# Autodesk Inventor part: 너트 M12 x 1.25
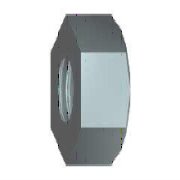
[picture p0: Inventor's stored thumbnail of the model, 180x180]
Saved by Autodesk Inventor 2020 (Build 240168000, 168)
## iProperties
Created: 2015-12
Part Number: 너트 M12 x 1.25
Material: 스테인리스강
Description: 6각 너트
Document SubType Name: Modeling
Standard: KS B 1012
Designer: mdu
Standards Organization: KS
Language: ko-KR
Size Designation: M12x1.25
Categories: <MemberInstance><Categories><Category DisplayName="조임쇠" InternalName="e4da775c-781d-43d5-af7c-5136215cf5a6" Mnemonic="FSTN"><Category DisplayName="너트" InternalN
Density: 8.08 g/cm^3
Appearance: 강철
IsCustomPart: 0
Author: mdu
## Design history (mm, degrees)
sketch "스케치1"
  geometry: L1 (10.97, 0)-(5.485, -9.5); L2 (5.485, -9.5)-(-5.485, -9.5); L3 (-5.485, -9.5)-(-10.97, 0); L4 (-10.97, 0)-(-5.485, 9.5); L5 (-5.485, 9.5)-(5.485, 9.5); L6 (5.485, 9.5)-(10.97, 0); 2 further points
  constraints: 12 end point, 1 coincident, 1 horizontal, 11 other
  dimensions: "d0" = 21.93931 distance of L1.start L3.end (= 1.1547 x SW)
extrude "본체" new body sketch "스케치1" distance "d1" = 10 (= KOH); taper "d2" = 0 deg
sketch "스케치2"
  geometry: 1 further point
hole "스레드" sketch "스케치2" diameter "d6" = 10.647; stored, may be unused: countersink angle "d10" = 82 deg, drill point angle "d12" = 118 deg; dims "d7" = 12.7, "d8" = 9.525, "d9" = 6.35, "d11" = 19.05
sketch "스케치3"
  geometry: L1 (0, 10.97)-(10, 10.97) reference; L2 (10, 5.485)-(10, 10.97) reference; L3 (-2, 0)-(12, 0) reference; L4 (9.151, 10.97)-(10, 9.5)
  constraints: 2 end point, 2 point on line
  dimensions: "d3" = 19 diameter of L4.end L3 (= SW01); "d4" = 30 deg angle of L2 L4 (= ANG2)
revolve "모따기3" sketch "스케치3" stored, may be unused: angle "d5" = 90 deg
workaxis "Work Axis1"
workplane "Work Plane1"
body "Solid1"
chamfer "모따기1" distance "d13" = 0.67658 (= -0.5 x GD1 + 0.5 x NND); stored, may be unused: angle "d14" = 30 deg, second distance "d21" = 0.67658 (= -0.5 x GD1 + 0.5 x NND)
chamfer "모따기2" distance "d15" = 0.67658 (= -0.5 x GD1 + 0.5 x NND); stored, may be unused: angle "d16" = 30 deg, second distance "d22" = 0.67658 (= -0.5 x GD1 + 0.5 x NND)
other parameters: "ANG2" = 30 deg [user parameter; used in 1 equation term], "NND" = 12 [user parameter; used in 4 equation terms], "KOH" = 10 [user parameter; used in 1 equation term], "SW" = 19 [user parameter; used in 3 equation terms], "SW01" = 19 (= SW) [user parameter; used in 1 equation term], "GD1" = 10.64684 (computed from THREADDIA, PTC, TOA) [user parameter; used in 4 equation terms], "d19" = 0, "d20" = 0, "d24" = 0, "d25" = 0, "GUL" = 0.67658 (= 0.541266 x PTC) [user parameter], "TPU" = 8 (computed from PTC) [user parameter], "TOA" = 30 deg [user parameter; used in 1 equation term], "PTC" = 1.25 [user parameter; used in 4 equation terms], "E0" = 21.945 (= 1.155 x SW) [user parameter], "THREADDIA" = 12 [user parameter; used in 1 equation term], "GAL" = 0.67658 (= 0.541266 x PTC) [user parameter]
